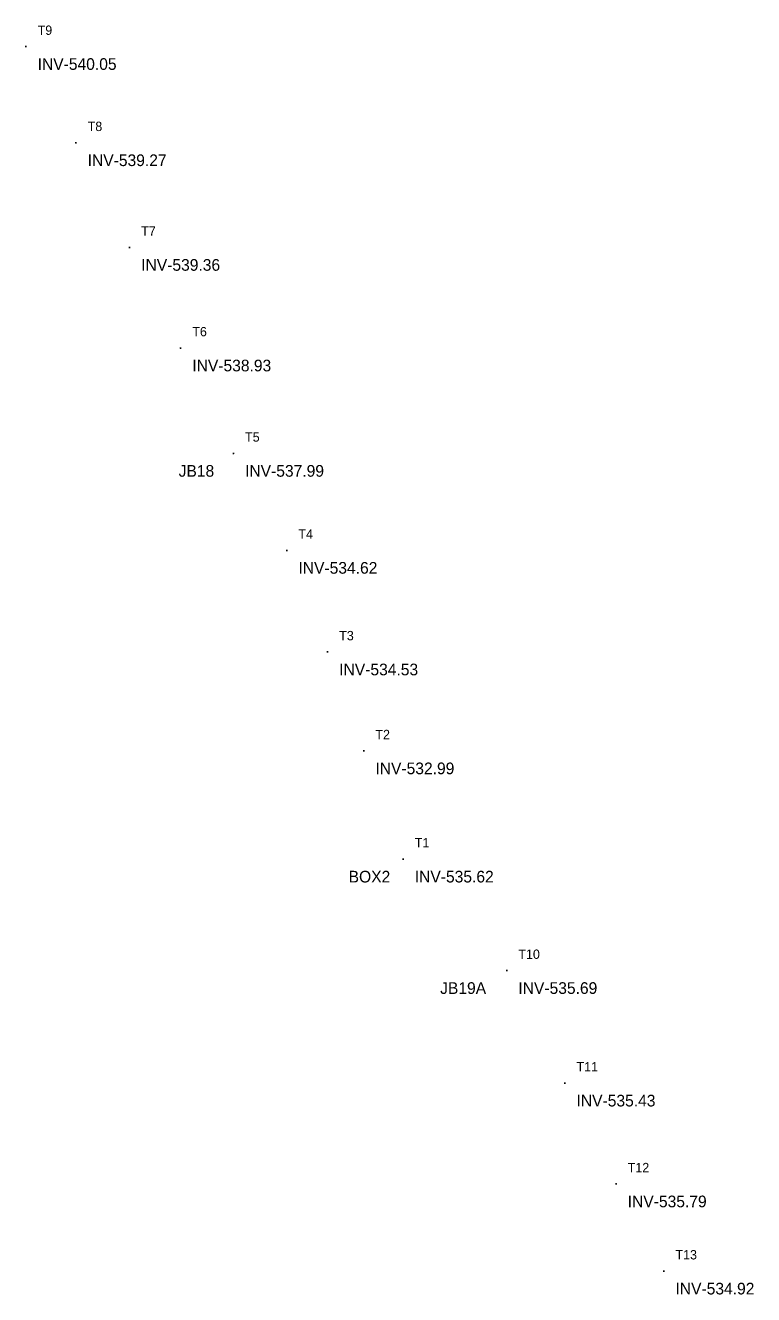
# Model space of a CAD drawing. Extents: x 1727664 to 1727976, y 653923 to 654467.
import ezdxf

# ---------------------------------------------------------------- set-up
doc = ezdxf.new("R2010")
doc.units = 0
for name, color, linetype in [('SURVEY - DRAINAGE - Storm Sewer - Points - Elevations', 7, 'Continuous'), ('SURVEY - DRAINAGE - Storm Sewer - Points - Locators', 7, 'Continuous'), ('SURVEY - DRAINAGE - Storm Sewer - Points - Numbers', 7, 'Continuous'), ('SURVEY - DRAINAGE - Storm Sewer Text', 7, 'Continuous')]:
    doc.layers.add(name, color=color, linetype=linetype)

msp = doc.modelspace()

# ---------------------------------------------------------------- linework, layer by layer
at = {"layer": 'SURVEY - DRAINAGE - Storm Sewer - Points - Locators'}
for p, q in [((1727664.55, 654457.69), (1727664.05, 654457.69)), ((1727664.3, 654457.44), (1727664.3, 654457.94)), ((1727664.3, 654457.69), (1727664.3, 654457.69)), ((1727664.3, 654457.69), (1727664.3, 654457.69)), ((1727685.99, 654416.5), (1727685.49, 654416.5)), ((1727685.74, 654416.25), (1727685.74, 654416.75)), ((1727685.74, 654416.5), (1727685.74, 654416.5)), ((1727685.74, 654416.5), (1727685.74, 654416.5)), ((1727708.92, 654371.67), (1727708.42, 654371.67)), ((1727708.67, 654371.42), (1727708.67, 654371.92)), ((1727708.67, 654371.67), (1727708.67, 654371.67)), ((1727708.67, 654371.67), (1727708.67, 654371.67)), ((1727730.82, 654328.59), (1727730.32, 654328.59)), ((1727730.57, 654328.34), (1727730.57, 654328.84)), ((1727730.57, 654328.59), (1727730.57, 654328.59)), ((1727730.57, 654328.59), (1727730.57, 654328.59)), ((1727753.43, 654283.47), (1727752.93, 654283.47)), ((1727753.18, 654283.22), (1727753.18, 654283.72)), ((1727753.18, 654283.47), (1727753.18, 654283.47)), ((1727753.18, 654283.47), (1727753.18, 654283.47)), ((1727776.3, 654241.94), (1727775.8, 654241.94)), ((1727776.05, 654241.69), (1727776.05, 654242.19)), ((1727776.05, 654241.94), (1727776.05, 654241.94)), ((1727776.05, 654241.94), (1727776.05, 654241.94)), ((1727793.77, 654198.42), (1727793.27, 654198.42)), ((1727793.52, 654198.17), (1727793.52, 654198.67)), ((1727793.52, 654198.42), (1727793.52, 654198.42)), ((1727793.52, 654198.42), (1727793.52, 654198.42)), ((1727809.28, 654156.07), (1727808.78, 654156.07)), ((1727809.03, 654155.82), (1727809.03, 654156.32)), ((1727809.03, 654156.07), (1727809.03, 654156.07)), ((1727809.03, 654156.07), (1727809.03, 654156.07)), ((1727826.15, 654109.7), (1727825.65, 654109.7)), ((1727825.9, 654109.45), (1727825.9, 654109.95)), ((1727825.9, 654109.7), (1727825.9, 654109.7)), ((1727825.9, 654109.7), (1727825.9, 654109.7)), ((1727870.53, 654061.99), (1727870.03, 654061.99)), ((1727870.28, 654061.74), (1727870.28, 654062.24)), ((1727870.28, 654061.99), (1727870.28, 654061.99)), ((1727870.28, 654061.99), (1727870.28, 654061.99)), ((1727895.45, 654013.78), (1727894.95, 654013.78)), ((1727895.2, 654013.53), (1727895.2, 654014.03)), ((1727895.2, 654013.78), (1727895.2, 654013.78)), ((1727895.2, 654013.78), (1727895.2, 654013.78)), ((1727917.39, 653970.61), (1727916.89, 653970.61)), ((1727917.14, 653970.36), (1727917.14, 653970.86)), ((1727917.14, 653970.61), (1727917.14, 653970.61)), ((1727917.14, 653970.61), (1727917.14, 653970.61)), ((1727937.85, 653933.28), (1727937.35, 653933.28)), ((1727937.6, 653933.03), (1727937.6, 653933.53)), ((1727937.6, 653933.28), (1727937.6, 653933.28)), ((1727937.6, 653933.28), (1727937.6, 653933.28))]:
    msp.add_line(p, q, dxfattribs=at)

# ---------------------------------------------------------------- texts
at = {"layer": 'SURVEY - DRAINAGE - Storm Sewer - Points - Elevations'}
for s, p in [('INV-540.05', (1727669.3, 654447.69)), ('INV-539.27', (1727690.74, 654406.5)), ('INV-539.36', (1727713.67, 654361.67)), ('INV-538.93', (1727735.57, 654318.59)), ('INV-537.99', (1727758.18, 654273.47)), ('INV-534.62', (1727781.05, 654231.94)), ('INV-534.53', (1727798.52, 654188.42)), ('INV-532.99', (1727814.03, 654146.07)), ('INV-535.62', (1727830.9, 654099.7)), ('INV-535.69', (1727875.28, 654051.99)), ('INV-535.43', (1727900.2, 654003.78)), ('INV-535.79', (1727922.14, 653960.61)), ('INV-534.92', (1727942.6, 653923.28))]:
    msp.add_text(s, height=5, dxfattribs=at).set_placement(p)
at = {"layer": 'SURVEY - DRAINAGE - Storm Sewer - Points - Numbers'}
for s, p in [('T9', (1727669.3, 654462.69)), ('T8', (1727690.74, 654421.5)), ('T7', (1727713.67, 654376.67)), ('T6', (1727735.57, 654333.59)), ('T5', (1727758.18, 654288.47)), ('T4', (1727781.05, 654246.94)), ('T3', (1727798.52, 654203.42)), ('T2', (1727814.03, 654161.07)), ('T1', (1727830.9, 654114.7)), ('T10', (1727875.28, 654066.99)), ('T11', (1727900.2, 654018.78)), ('T12', (1727922.14, 653975.61)), ('T13', (1727942.6, 653938.28))]:
    msp.add_text(s, height=4, dxfattribs=at).set_placement(p)
at = {"layer": 'SURVEY - DRAINAGE - Storm Sewer Text'}
for s, p in [('JB18', (1727729.72, 654273.47)), ('BOX2', (1727802.56, 654099.7)), ('JB19A', (1727841.77, 654051.99))]:
    msp.add_text(s, height=5, dxfattribs=at).set_placement(p)

doc.saveas('drawing.dxf')
